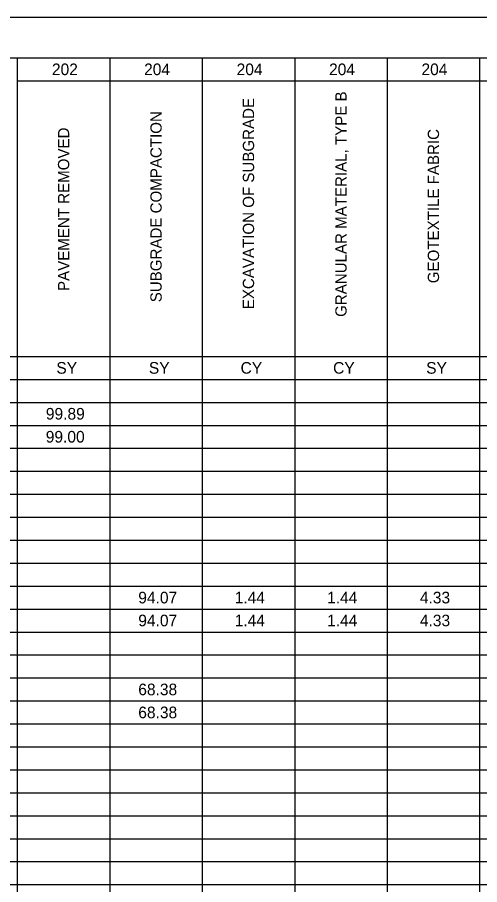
# Model space of a CAD drawing. Extents: x 0 to 34, y 0 to 22.
# Drawn here: x 10.32 to 16.02, y 11.28 to 22 of the extents above; entities that cross this region are included whole.
import ezdxf

# ---------------------------------------------------------------- set-up
doc = ezdxf.new("R2010")
doc.units = 0
for name, color, linetype in [('SH_Border', 7, 'Continuous'), ('SH_Cut_Line', 7, 'Continuous'), ('SH_Text', 7, 'Continuous')]:
    doc.layers.add(name, color=color, linetype=linetype)

msp = doc.modelspace()

# ---------------------------------------------------------------- linework, layer by layer
at = {"layer": 'SH_Border'}
msp.add_lwpolyline([(1.5, 21.5), (33.5, 21.5), (33.5, 0.5), (1.5, 0.5)], close=True, dxfattribs=at)
at = {"layer": 'SH_Cut_Line'}
msp.add_lwpolyline([(0, 0), (34, 0), (34, 22), (0, 22)], close=True, dxfattribs=at)
at = {"layer": 'SH_Text'}
for p, q in [((8.033, 21.5), (10.315, 21.5)), ((10.315, 21.5), (11.457, 21.5)), ((10.315, 21.5), (10.315, 21.216)), ((11.457, 21.5), (13.739, 21.5)), ((11.457, 21.5), (11.457, 21.216)), ((12.598, 21.5), (12.598, 21.216)), ((13.739, 21.5), (14.881, 21.5)), ((13.739, 21.5), (13.739, 21.216)), ((14.881, 21.5), (16.022, 21.5)), ((14.881, 21.5), (14.881, 21.216)), ((16.022, 21.5), (24.011, 21.5)), ((16.022, 21.5), (16.022, 21.216)), ((10.315, 21.216), (11.457, 21.216)), ((10.315, 21.216), (10.315, 20.932)), ((11.457, 21.216), (13.739, 21.216)), ((11.457, 21.216), (11.457, 20.932)), ((12.598, 21.216), (12.598, 20.932)), ((13.739, 21.216), (14.881, 21.216)), ((13.739, 21.216), (13.739, 20.932)), ((14.881, 21.216), (16.022, 21.216)), ((14.881, 21.216), (14.881, 20.932)), ((16.022, 21.216), (24.011, 21.216)), ((16.022, 21.216), (16.022, 20.932)), ((10.315, 20.932), (10.315, 20.649)), ((11.457, 20.932), (11.457, 20.649)), ((12.598, 20.932), (12.598, 20.649)), ((13.739, 20.932), (13.739, 20.649)), ((14.881, 20.932), (14.881, 20.649)), ((16.022, 20.932), (16.022, 20.649)), ((10.315, 20.649), (10.315, 20.081)), ((11.457, 20.649), (11.457, 20.081)), ((12.598, 20.649), (12.598, 20.081)), ((13.739, 20.649), (13.739, 20.081)), ((14.881, 20.649), (14.881, 20.081)), ((16.022, 20.649), (16.022, 20.081)), ((10.315, 20.081), (10.315, 19.797)), ((11.457, 20.081), (11.457, 19.797)), ((12.598, 20.081), (12.598, 19.797)), ((13.739, 20.081), (13.739, 19.797)), ((14.881, 20.081), (14.881, 19.797)), ((16.022, 20.081), (16.022, 19.797)), ((10.315, 19.797), (10.315, 19.514)), ((11.457, 19.797), (11.457, 19.514)), ((12.598, 19.797), (12.598, 19.514)), ((13.739, 19.797), (13.739, 19.514)), ((14.881, 19.797), (14.881, 19.514)), ((16.022, 19.797), (16.022, 19.514)), ((10.315, 19.514), (10.315, 19.23)), ((11.457, 19.514), (11.457, 19.23)), ((12.598, 19.514), (12.598, 19.23)), ((13.739, 19.514), (13.739, 19.23)), ((14.881, 19.514), (14.881, 19.23)), ((16.022, 19.514), (16.022, 19.23)), ((10.315, 19.23), (10.315, 18.946)), ((11.457, 19.23), (11.457, 18.946)), ((12.598, 19.23), (12.598, 18.946)), ((13.739, 19.23), (13.739, 18.946)), ((14.881, 19.23), (14.881, 18.946)), ((16.022, 19.23), (16.022, 18.946)), ((10.315, 18.946), (10.315, 18.662)), ((11.457, 18.946), (11.457, 18.662)), ((12.598, 18.946), (12.598, 18.662)), ((13.739, 18.946), (13.739, 18.662)), ((14.881, 18.946), (14.881, 18.662)), ((16.022, 18.946), (16.022, 18.662)), ((10.315, 18.662), (10.315, 18.378)), ((11.457, 18.662), (11.457, 18.378)), ((12.598, 18.662), (12.598, 18.378)), ((13.739, 18.662), (13.739, 18.378)), ((14.881, 18.662), (14.881, 18.378)), ((16.022, 18.662), (16.022, 18.378)), ((10.315, 18.378), (10.315, 18.095)), ((11.457, 18.378), (11.457, 18.095)), ((12.598, 18.378), (12.598, 18.095)), ((13.739, 18.378), (13.739, 18.095)), ((14.881, 18.378), (14.881, 18.095)), ((16.022, 18.378), (16.022, 18.095)), ((10.315, 18.095), (10.315, 17.811)), ((11.457, 18.095), (11.457, 17.811)), ((12.598, 18.095), (12.598, 17.811)), ((13.739, 18.095), (13.739, 17.811)), ((14.881, 18.095), (14.881, 17.811)), ((16.022, 18.095), (16.022, 17.811)), ((8.033, 17.811), (10.315, 17.811)), ((10.315, 17.811), (11.457, 17.811)), ((10.315, 17.811), (10.315, 17.527)), ((11.457, 17.811), (13.739, 17.811)), ((11.457, 17.811), (11.457, 17.527)), ((12.598, 17.811), (12.598, 17.527)), ((13.739, 17.811), (14.881, 17.811)), ((13.739, 17.811), (13.739, 17.527)), ((14.881, 17.811), (16.022, 17.811)), ((14.881, 17.811), (14.881, 17.527)), ((16.022, 17.811), (24.011, 17.811)), ((16.022, 17.811), (16.022, 17.527)), ((8.033, 17.527), (10.315, 17.527)), ((10.315, 17.527), (11.457, 17.527)), ((10.315, 17.527), (10.315, 17.243)), ((11.457, 17.527), (13.739, 17.527)), ((11.457, 17.527), (11.457, 17.243)), ((12.598, 17.527), (12.598, 17.243)), ((13.739, 17.527), (14.881, 17.527)), ((13.739, 17.527), (13.739, 17.243)), ((14.881, 17.527), (16.022, 17.527)), ((14.881, 17.527), (14.881, 17.243)), ((16.022, 17.527), (24.011, 17.527)), ((16.022, 17.527), (16.022, 17.243)), ((8.033, 17.243), (10.315, 17.243)), ((10.315, 17.243), (11.457, 17.243)), ((10.315, 17.243), (10.315, 16.959)), ((11.457, 17.243), (13.739, 17.243)), ((11.457, 17.243), (11.457, 16.959)), ((12.598, 17.243), (12.598, 16.959)), ((13.739, 17.243), (14.881, 17.243)), ((13.739, 17.243), (13.739, 16.959)), ((14.881, 17.243), (16.022, 17.243)), ((14.881, 17.243), (14.881, 16.959)), ((16.022, 17.243), (24.011, 17.243)), ((16.022, 17.243), (16.022, 16.959)), ((8.033, 16.959), (10.315, 16.959)), ((10.315, 16.959), (11.457, 16.959)), ((10.315, 16.959), (10.315, 16.676)), ((11.457, 16.959), (13.739, 16.959)), ((11.457, 16.959), (11.457, 16.676)), ((12.598, 16.959), (12.598, 16.676)), ((13.739, 16.959), (14.881, 16.959)), ((13.739, 16.959), (13.739, 16.676)), ((14.881, 16.959), (16.022, 16.959)), ((14.881, 16.959), (14.881, 16.676)), ((16.022, 16.959), (24.011, 16.959)), ((16.022, 16.959), (16.022, 16.676)), ((8.033, 16.676), (10.315, 16.676)), ((10.315, 16.676), (11.457, 16.676)), ((10.315, 16.676), (10.315, 16.108)), ((11.457, 16.676), (13.739, 16.676)), ((11.457, 16.676), (11.457, 16.108)), ((12.598, 16.676), (12.598, 16.108)), ((13.739, 16.676), (14.881, 16.676)), ((13.739, 16.676), (13.739, 16.108)), ((14.881, 16.676), (16.022, 16.676)), ((14.881, 16.676), (14.881, 16.108)), ((16.022, 16.676), (24.011, 16.676)), ((16.022, 16.676), (16.022, 16.108)), ((8.033, 16.392), (10.315, 16.392)), ((10.315, 16.392), (11.457, 16.392)), ((11.457, 16.392), (13.739, 16.392)), ((13.739, 16.392), (14.881, 16.392)), ((14.881, 16.392), (16.022, 16.392)), ((16.022, 16.392), (24.011, 16.392)), ((8.033, 16.108), (10.315, 16.108)), ((10.315, 16.108), (11.457, 16.108)), ((10.315, 16.108), (10.315, 15.824)), ((11.457, 16.108), (13.739, 16.108)), ((11.457, 16.108), (11.457, 15.824)), ((12.598, 16.108), (12.598, 15.824)), ((13.739, 16.108), (14.881, 16.108)), ((13.739, 16.108), (13.739, 15.824)), ((14.881, 16.108), (16.022, 16.108)), ((14.881, 16.108), (14.881, 15.824)), ((16.022, 16.108), (24.011, 16.108)), ((16.022, 16.108), (16.022, 15.824)), ((8.033, 15.824), (10.315, 15.824)), ((10.315, 15.824), (11.457, 15.824)), ((10.315, 15.824), (10.315, 15.541)), ((11.457, 15.824), (13.739, 15.824)), ((11.457, 15.824), (11.457, 15.541)), ((12.598, 15.824), (12.598, 15.541)), ((13.739, 15.824), (14.881, 15.824)), ((13.739, 15.824), (13.739, 15.541)), ((14.881, 15.824), (16.022, 15.824)), ((14.881, 15.824), (14.881, 15.541)), ((16.022, 15.824), (24.011, 15.824)), ((16.022, 15.824), (16.022, 15.541)), ((8.033, 15.541), (10.315, 15.541)), ((10.315, 15.541), (11.457, 15.541)), ((10.315, 15.541), (10.315, 15.257)), ((11.457, 15.541), (13.739, 15.541)), ((11.457, 15.541), (11.457, 15.257)), ((12.598, 15.541), (12.598, 15.257)), ((13.739, 15.541), (14.881, 15.541)), ((13.739, 15.541), (13.739, 15.257)), ((14.881, 15.541), (16.022, 15.541)), ((14.881, 15.541), (14.881, 15.257)), ((16.022, 15.541), (24.011, 15.541)), ((16.022, 15.541), (16.022, 15.257)), ((8.033, 15.257), (10.315, 15.257)), ((10.315, 15.257), (11.457, 15.257)), ((10.315, 15.257), (10.315, 14.689)), ((11.457, 15.257), (13.739, 15.257)), ((11.457, 15.257), (11.457, 14.689)), ((12.598, 15.257), (12.598, 14.689)), ((13.739, 15.257), (14.881, 15.257)), ((13.739, 15.257), (13.739, 14.689)), ((14.881, 15.257), (16.022, 15.257)), ((14.881, 15.257), (14.881, 14.689)), ((16.022, 15.257), (24.011, 15.257)), ((16.022, 15.257), (16.022, 14.689)), ((8.033, 14.973), (10.315, 14.973)), ((10.315, 14.973), (11.457, 14.973)), ((11.457, 14.973), (13.739, 14.973)), ((13.739, 14.973), (14.881, 14.973)), ((14.881, 14.973), (16.022, 14.973)), ((16.022, 14.973), (24.011, 14.973)), ((8.033, 14.689), (10.315, 14.689)), ((10.315, 14.689), (11.457, 14.689)), ((10.315, 14.689), (10.315, 14.405)), ((11.457, 14.689), (13.739, 14.689)), ((11.457, 14.689), (11.457, 14.405)), ((12.598, 14.689), (12.598, 14.405)), ((13.739, 14.689), (14.881, 14.689)), ((13.739, 14.689), (13.739, 14.405)), ((14.881, 14.689), (16.022, 14.689)), ((14.881, 14.689), (14.881, 14.405)), ((16.022, 14.689), (24.011, 14.689)), ((16.022, 14.689), (16.022, 14.405)), ((8.033, 14.405), (10.315, 14.405)), ((10.315, 14.405), (11.457, 14.405)), ((10.315, 14.405), (10.315, 14.122)), ((11.457, 14.405), (13.739, 14.405)), ((11.457, 14.405), (11.457, 14.122)), ((12.598, 14.405), (12.598, 14.122)), ((13.739, 14.405), (14.881, 14.405)), ((13.739, 14.405), (13.739, 14.122)), ((14.881, 14.405), (16.022, 14.405)), ((14.881, 14.405), (14.881, 14.122)), ((16.022, 14.405), (24.011, 14.405)), ((16.022, 14.405), (16.022, 14.122)), ((8.033, 14.122), (10.315, 14.122)), ((10.315, 14.122), (11.457, 14.122)), ((10.315, 14.122), (10.315, 13.838)), ((11.457, 14.122), (13.739, 14.122)), ((11.457, 14.122), (11.457, 13.838)), ((12.598, 14.122), (12.598, 13.838)), ((13.739, 14.122), (14.881, 14.122)), ((13.739, 14.122), (13.739, 13.838)), ((14.881, 14.122), (16.022, 14.122)), ((14.881, 14.122), (14.881, 13.838)), ((16.022, 14.122), (24.011, 14.122)), ((16.022, 14.122), (16.022, 13.838)), ((8.033, 13.838), (10.315, 13.838)), ((10.315, 13.838), (11.457, 13.838)), ((10.315, 13.838), (10.315, 12.986)), ((11.457, 13.838), (13.739, 13.838)), ((11.457, 13.838), (11.457, 12.986)), ((12.598, 13.838), (12.598, 12.986)), ((13.739, 13.838), (14.881, 13.838)), ((13.739, 13.838), (13.739, 12.986)), ((14.881, 13.838), (16.022, 13.838)), ((14.881, 13.838), (14.881, 12.986)), ((16.022, 13.838), (24.011, 13.838)), ((16.022, 13.838), (16.022, 12.986)), ((8.033, 13.554), (10.315, 13.554)), ((10.315, 13.554), (11.457, 13.554)), ((11.457, 13.554), (13.739, 13.554)), ((13.739, 13.554), (14.881, 13.554)), ((14.881, 13.554), (16.022, 13.554)), ((16.022, 13.554), (24.011, 13.554)), ((8.033, 13.27), (10.315, 13.27)), ((10.315, 13.27), (11.457, 13.27)), ((11.457, 13.27), (13.739, 13.27)), ((13.739, 13.27), (14.881, 13.27)), ((14.881, 13.27), (16.022, 13.27)), ((16.022, 13.27), (24.011, 13.27)), ((8.033, 12.986), (10.315, 12.986)), ((10.315, 12.986), (11.457, 12.986)), ((10.315, 12.986), (10.315, 12.703)), ((11.457, 12.986), (13.739, 12.986)), ((11.457, 12.986), (11.457, 12.703)), ((12.598, 12.986), (12.598, 12.703)), ((13.739, 12.986), (14.881, 12.986)), ((13.739, 12.986), (13.739, 12.703)), ((14.881, 12.986), (16.022, 12.986)), ((14.881, 12.986), (14.881, 12.703)), ((16.022, 12.986), (24.011, 12.986)), ((16.022, 12.986), (16.022, 12.703)), ((8.033, 12.703), (10.315, 12.703)), ((10.315, 12.703), (11.457, 12.703)), ((10.315, 12.703), (10.315, 11.568)), ((11.457, 12.703), (13.739, 12.703)), ((11.457, 12.703), (11.457, 11.568)), ((12.598, 12.703), (12.598, 11.568)), ((13.739, 12.703), (14.881, 12.703)), ((13.739, 12.703), (13.739, 11.568)), ((14.881, 12.703), (16.022, 12.703)), ((14.881, 12.703), (14.881, 11.568)), ((16.022, 12.703), (24.011, 12.703)), ((16.022, 12.703), (16.022, 11.568)), ((8.033, 12.419), (10.315, 12.419)), ((10.315, 12.419), (11.457, 12.419)), ((11.457, 12.419), (13.739, 12.419)), ((13.739, 12.419), (14.881, 12.419)), ((14.881, 12.419), (16.022, 12.419)), ((16.022, 12.419), (24.011, 12.419)), ((8.033, 12.135), (10.315, 12.135)), ((10.315, 12.135), (11.457, 12.135)), ((11.457, 12.135), (13.739, 12.135)), ((13.739, 12.135), (14.881, 12.135)), ((14.881, 12.135), (16.022, 12.135)), ((16.022, 12.135), (24.011, 12.135)), ((8.033, 11.851), (10.315, 11.851)), ((10.315, 11.851), (11.457, 11.851)), ((11.457, 11.851), (13.739, 11.851)), ((13.739, 11.851), (14.881, 11.851)), ((14.881, 11.851), (16.022, 11.851)), ((16.022, 11.851), (24.011, 11.851)), ((8.033, 11.568), (10.315, 11.568)), ((10.315, 11.568), (11.457, 11.568)), ((10.315, 11.568), (10.315, 11.284)), ((11.457, 11.568), (13.739, 11.568)), ((11.457, 11.568), (11.457, 11.284)), ((12.598, 11.568), (12.598, 11.284)), ((13.739, 11.568), (14.881, 11.568)), ((13.739, 11.568), (13.739, 11.284)), ((14.881, 11.568), (16.022, 11.568)), ((14.881, 11.568), (14.881, 11.284)), ((16.022, 11.568), (24.011, 11.568)), ((16.022, 11.568), (16.022, 11.284)), ((8.033, 11.284), (10.315, 11.284)), ((10.315, 11.284), (11.457, 11.284)), ((10.315, 11.284), (10.315, 10.149)), ((11.457, 11.284), (13.739, 11.284)), ((11.457, 11.284), (11.457, 10.149)), ((12.598, 11.284), (12.598, 10.149)), ((13.739, 11.284), (14.881, 11.284)), ((13.739, 11.284), (13.739, 10.149)), ((14.881, 11.284), (16.022, 11.284)), ((14.881, 11.284), (14.881, 10.149)), ((16.022, 11.284), (24.011, 11.284)), ((16.022, 11.284), (16.022, 10.149))]:
    msp.add_line(p, q, dxfattribs=at)

# ---------------------------------------------------------------- texts
for s, p in [('202', (10.742, 21.286)), ('204', (11.88, 21.286)), ('204', (13.022, 21.286)), ('204', (14.163, 21.286)), ('204', (15.304, 21.286)), ('SY', (10.797, 17.597)), ('SY', (11.939, 17.597)), ('CY', (13.071, 17.597)), ('CY', (14.213, 17.597)), ('SY', (15.362, 17.597)), ('99.89', (10.667, 17.03)), ('99.00', (10.666, 16.746)), ('94.07', (11.808, 14.759)), ('1.44', (12.998, 14.759)), ('1.44', (14.139, 14.759)), ('4.33', (15.284, 14.759)), ('94.07', (11.808, 14.476)), ('1.44', (12.998, 14.476)), ('1.44', (14.139, 14.476)), ('4.33', (15.284, 14.476)), ('68.38', (11.808, 13.624)), ('68.38', (11.808, 13.34))]:
    msp.add_text(s, height=0.1436, dxfattribs=at).set_placement(p)
for s, p in [('GRANULAR MATERIAL, TYPE B', (14.38, 18.299)), ('EXCAVATION OF SUBGRADE', (13.238, 18.394)), ('SUBGRADE COMPACTION', (12.097, 18.48)), ('PAVEMENT REMOVED', (10.956, 18.619)), ('GEOTEXTILE FABRIC', (15.521, 18.715))]:
    msp.add_text(s, height=0.13938, rotation=90, dxfattribs=at).set_placement(p)

doc.saveas('drawing.dxf')
